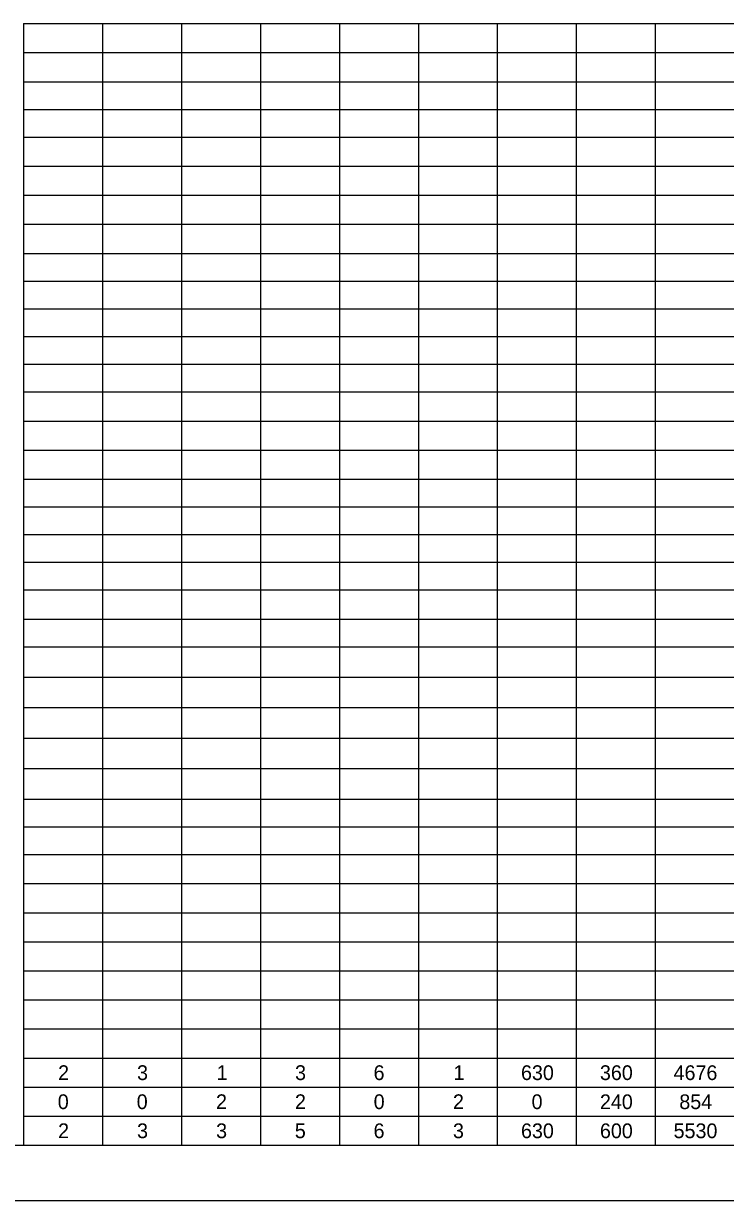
# Model space of a CAD drawing. Extents: x 0 to 34, y 0 to 22.
# Drawn here: x 13.35 to 19.73, y 0 to 10.69 of the extents above; entities that cross this region are included whole.
import ezdxf

# ---------------------------------------------------------------- set-up
doc = ezdxf.new("R2010")
doc.units = 0
for name, color, linetype in [('SH_Border', 7, 'Continuous'), ('SH_Cut_Line', 7, 'Continuous'), ('SH_Text', 7, 'Continuous')]:
    doc.layers.add(name, color=color, linetype=linetype)

msp = doc.modelspace()

# ---------------------------------------------------------------- linework, layer by layer
at = {"layer": 'SH_Border'}
msp.add_lwpolyline([(1.5, 21.5), (33.5, 21.5), (33.5, 0.5), (1.5, 0.5)], close=True, dxfattribs=at)
at = {"layer": 'SH_Cut_Line'}
msp.add_lwpolyline([(0, 0), (34, 0), (34, 22), (0, 22)], close=True, dxfattribs=at)
at = {"layer": 'SH_Text'}
for p, q in [((13.352, 10.692), (14.069, 10.692)), ((13.352, 10.692), (13.352, 10.428)), ((14.069, 10.692), (15.504, 10.692)), ((14.069, 10.692), (14.069, 10.428)), ((14.787, 10.692), (14.787, 10.428)), ((15.504, 10.692), (21.958, 10.692)), ((15.504, 10.692), (15.504, 10.428)), ((16.221, 10.692), (16.221, 10.428)), ((16.938, 10.692), (16.938, 10.428)), ((17.655, 10.692), (17.655, 10.428)), ((18.372, 10.692), (18.372, 10.428)), ((19.09, 10.692), (19.09, 10.428)), ((13.352, 10.428), (14.069, 10.428)), ((13.352, 10.428), (13.352, 10.164)), ((14.069, 10.428), (15.504, 10.428)), ((14.069, 10.428), (14.069, 10.164)), ((14.787, 10.428), (14.787, 10.164)), ((15.504, 10.428), (21.958, 10.428)), ((15.504, 10.428), (15.504, 10.164)), ((16.221, 10.428), (16.221, 10.164)), ((16.938, 10.428), (16.938, 10.164)), ((17.655, 10.428), (17.655, 10.164)), ((18.372, 10.428), (18.372, 10.164)), ((19.09, 10.428), (19.09, 10.164)), ((13.352, 10.164), (14.069, 10.164)), ((13.352, 10.164), (13.352, 9.396)), ((14.069, 10.164), (15.504, 10.164)), ((14.069, 10.164), (14.069, 9.396)), ((14.787, 10.164), (14.787, 9.396)), ((15.504, 10.164), (21.958, 10.164)), ((15.504, 10.164), (15.504, 9.396)), ((16.221, 10.164), (16.221, 9.396)), ((16.938, 10.164), (16.938, 9.396)), ((17.655, 10.164), (17.655, 9.396)), ((18.372, 10.164), (18.372, 9.396)), ((19.09, 10.164), (19.09, 9.396)), ((13.352, 9.912), (14.069, 9.912)), ((14.069, 9.912), (15.504, 9.912)), ((15.504, 9.912), (21.958, 9.912)), ((13.352, 9.66), (14.069, 9.66)), ((14.069, 9.66), (15.504, 9.66)), ((15.504, 9.66), (21.958, 9.66)), ((13.352, 9.396), (14.069, 9.396)), ((13.352, 9.396), (13.352, 9.132)), ((14.069, 9.396), (15.504, 9.396)), ((14.069, 9.396), (14.069, 9.132)), ((14.787, 9.396), (14.787, 9.132)), ((15.504, 9.396), (21.958, 9.396)), ((15.504, 9.396), (15.504, 9.132)), ((16.221, 9.396), (16.221, 9.132)), ((16.938, 9.396), (16.938, 9.132)), ((17.655, 9.396), (17.655, 9.132)), ((18.372, 9.396), (18.372, 9.132)), ((19.09, 9.396), (19.09, 9.132)), ((13.352, 9.132), (14.069, 9.132)), ((13.352, 9.132), (13.352, 8.868)), ((14.069, 9.132), (15.504, 9.132)), ((14.069, 9.132), (14.069, 8.868)), ((14.787, 9.132), (14.787, 8.868)), ((15.504, 9.132), (21.958, 9.132)), ((15.504, 9.132), (15.504, 8.868)), ((16.221, 9.132), (16.221, 8.868)), ((16.938, 9.132), (16.938, 8.868)), ((17.655, 9.132), (17.655, 8.868)), ((18.372, 9.132), (18.372, 8.868)), ((19.09, 9.132), (19.09, 8.868)), ((13.352, 8.868), (14.069, 8.868)), ((13.352, 8.868), (13.352, 8.604)), ((14.069, 8.868), (15.504, 8.868)), ((14.069, 8.868), (14.069, 8.604)), ((14.787, 8.868), (14.787, 8.604)), ((15.504, 8.868), (21.958, 8.868)), ((15.504, 8.868), (15.504, 8.604)), ((16.221, 8.868), (16.221, 8.604)), ((16.938, 8.868), (16.938, 8.604)), ((17.655, 8.868), (17.655, 8.604)), ((18.372, 8.868), (18.372, 8.604)), ((19.09, 8.868), (19.09, 8.604)), ((13.352, 8.604), (14.069, 8.604)), ((13.352, 8.604), (13.352, 7.081)), ((14.069, 8.604), (15.504, 8.604)), ((14.069, 8.604), (14.069, 7.081)), ((14.787, 8.604), (14.787, 7.081)), ((15.504, 8.604), (21.958, 8.604)), ((15.504, 8.604), (15.504, 7.081)), ((16.221, 8.604), (16.221, 7.081)), ((16.938, 8.604), (16.938, 7.081)), ((17.655, 8.604), (17.655, 7.081)), ((18.372, 8.604), (18.372, 7.081)), ((19.09, 8.604), (19.09, 7.081)), ((13.352, 8.352), (14.069, 8.352)), ((14.069, 8.352), (15.504, 8.352)), ((15.504, 8.352), (21.958, 8.352)), ((13.352, 8.1), (14.069, 8.1)), ((14.069, 8.1), (15.504, 8.1)), ((15.504, 8.1), (21.958, 8.1)), ((13.352, 7.849), (14.069, 7.849)), ((14.069, 7.849), (15.504, 7.849)), ((15.504, 7.849), (21.958, 7.849)), ((13.352, 7.597), (14.069, 7.597)), ((14.069, 7.597), (15.504, 7.597)), ((15.504, 7.597), (21.958, 7.597)), ((13.352, 7.345), (14.069, 7.345)), ((14.069, 7.345), (15.504, 7.345)), ((15.504, 7.345), (21.958, 7.345)), ((13.352, 7.081), (14.069, 7.081)), ((13.352, 7.081), (13.352, 6.817)), ((14.069, 7.081), (15.504, 7.081)), ((14.069, 7.081), (14.069, 6.817)), ((14.787, 7.081), (14.787, 6.817)), ((15.504, 7.081), (21.958, 7.081)), ((15.504, 7.081), (15.504, 6.817)), ((16.221, 7.081), (16.221, 6.817)), ((16.938, 7.081), (16.938, 6.817)), ((17.655, 7.081), (17.655, 6.817)), ((18.372, 7.081), (18.372, 6.817)), ((19.09, 7.081), (19.09, 6.817)), ((13.352, 6.817), (14.069, 6.817)), ((13.352, 6.817), (13.352, 5.282)), ((14.069, 6.817), (15.504, 6.817)), ((14.069, 6.817), (14.069, 5.282)), ((14.787, 6.817), (14.787, 5.282)), ((15.504, 6.817), (21.958, 6.817)), ((15.504, 6.817), (15.504, 5.282)), ((16.221, 6.817), (16.221, 5.282)), ((16.938, 6.817), (16.938, 5.282)), ((17.655, 6.817), (17.655, 5.282)), ((18.372, 6.817), (18.372, 5.282)), ((19.09, 6.817), (19.09, 5.282)), ((13.352, 6.553), (14.069, 6.553)), ((14.069, 6.553), (15.504, 6.553)), ((15.504, 6.553), (21.958, 6.553)), ((13.352, 6.301), (14.069, 6.301)), ((14.069, 6.301), (15.504, 6.301)), ((15.504, 6.301), (21.958, 6.301)), ((13.352, 6.049), (14.069, 6.049)), ((14.069, 6.049), (15.504, 6.049)), ((15.504, 6.049), (21.958, 6.049)), ((13.352, 5.798), (14.069, 5.798)), ((14.069, 5.798), (15.504, 5.798)), ((15.504, 5.798), (21.958, 5.798)), ((13.352, 5.546), (14.069, 5.546)), ((14.069, 5.546), (15.504, 5.546)), ((15.504, 5.546), (21.958, 5.546)), ((13.352, 5.282), (14.069, 5.282)), ((13.352, 5.282), (13.352, 4.477)), ((14.069, 5.282), (15.504, 5.282)), ((14.069, 5.282), (14.069, 4.477)), ((14.787, 5.282), (14.787, 4.477)), ((15.504, 5.282), (21.958, 5.282)), ((15.504, 5.282), (15.504, 4.477)), ((16.221, 5.282), (16.221, 4.477)), ((16.938, 5.282), (16.938, 4.477)), ((17.655, 5.282), (17.655, 4.477)), ((18.372, 5.282), (18.372, 4.477)), ((19.09, 5.282), (19.09, 4.477)), ((13.352, 5.03), (14.069, 5.03)), ((14.069, 5.03), (15.504, 5.03)), ((15.504, 5.03), (21.958, 5.03)), ((13.352, 4.753), (14.069, 4.753)), ((14.069, 4.753), (15.504, 4.753)), ((15.504, 4.753), (21.958, 4.753)), ((13.352, 4.477), (14.069, 4.477)), ((13.352, 4.477), (13.352, 3.646)), ((14.069, 4.477), (15.504, 4.477)), ((14.069, 4.477), (14.069, 3.646)), ((14.787, 4.477), (14.787, 3.646)), ((15.504, 4.477), (21.958, 4.477)), ((15.504, 4.477), (15.504, 3.646)), ((16.221, 4.477), (16.221, 3.646)), ((16.938, 4.477), (16.938, 3.646)), ((17.655, 4.477), (17.655, 3.646)), ((18.372, 4.477), (18.372, 3.646)), ((19.09, 4.477), (19.09, 3.646)), ((13.352, 4.2), (14.069, 4.2)), ((14.069, 4.2), (15.504, 4.2)), ((15.504, 4.2), (21.958, 4.2)), ((13.352, 3.923), (14.069, 3.923)), ((14.069, 3.923), (15.504, 3.923)), ((15.504, 3.923), (21.958, 3.923)), ((13.352, 3.646), (14.069, 3.646)), ((13.352, 3.646), (13.352, 2.35)), ((14.069, 3.646), (15.504, 3.646)), ((14.069, 3.646), (14.069, 2.35)), ((14.787, 3.646), (14.787, 2.35)), ((15.504, 3.646), (21.958, 3.646)), ((15.504, 3.646), (15.504, 2.35)), ((16.221, 3.646), (16.221, 2.35)), ((16.938, 3.646), (16.938, 2.35)), ((17.655, 3.646), (17.655, 2.35)), ((18.372, 3.646), (18.372, 2.35)), ((19.09, 3.646), (19.09, 2.35)), ((13.352, 3.395), (14.069, 3.395)), ((14.069, 3.395), (15.504, 3.395)), ((15.504, 3.395), (21.958, 3.395)), ((13.352, 3.143), (14.069, 3.143)), ((14.069, 3.143), (15.504, 3.143)), ((15.504, 3.143), (21.958, 3.143)), ((13.352, 2.879), (14.069, 2.879)), ((14.069, 2.879), (15.504, 2.879)), ((15.504, 2.879), (21.958, 2.879)), ((13.352, 2.614), (14.069, 2.614)), ((14.069, 2.614), (15.504, 2.614)), ((15.504, 2.614), (21.958, 2.614)), ((13.352, 2.35), (14.069, 2.35)), ((13.352, 2.35), (13.352, 1.822)), ((14.069, 2.35), (15.504, 2.35)), ((14.069, 2.35), (14.069, 1.822)), ((14.787, 2.35), (14.787, 1.822)), ((15.504, 2.35), (21.958, 2.35)), ((15.504, 2.35), (15.504, 1.822)), ((16.221, 2.35), (16.221, 1.822)), ((16.938, 2.35), (16.938, 1.822)), ((17.655, 2.35), (17.655, 1.822)), ((18.372, 2.35), (18.372, 1.822)), ((19.09, 2.35), (19.09, 1.822)), ((13.352, 2.086), (14.069, 2.086)), ((14.069, 2.086), (15.504, 2.086)), ((15.504, 2.086), (21.958, 2.086)), ((13.352, 1.822), (14.069, 1.822)), ((13.352, 1.822), (13.352, 1.558)), ((14.069, 1.822), (15.504, 1.822)), ((14.069, 1.822), (14.069, 1.558)), ((14.787, 1.822), (14.787, 1.558)), ((15.504, 1.822), (21.958, 1.822)), ((15.504, 1.822), (15.504, 1.558)), ((16.221, 1.822), (16.221, 1.558)), ((16.938, 1.822), (16.938, 1.558)), ((17.655, 1.822), (17.655, 1.558)), ((18.372, 1.822), (18.372, 1.558)), ((19.09, 1.822), (19.09, 1.558)), ((13.352, 1.558), (14.069, 1.558)), ((13.352, 1.558), (13.352, 1.029)), ((14.069, 1.558), (15.504, 1.558)), ((14.069, 1.558), (14.069, 1.029)), ((14.787, 1.558), (14.787, 1.029)), ((15.504, 1.558), (21.958, 1.558)), ((15.504, 1.558), (15.504, 1.029)), ((16.221, 1.558), (16.221, 1.029)), ((16.938, 1.558), (16.938, 1.029)), ((17.655, 1.558), (17.655, 1.029)), ((18.372, 1.558), (18.372, 1.029)), ((19.09, 1.558), (19.09, 1.029)), ((13.352, 1.293), (14.069, 1.293)), ((14.069, 1.293), (15.504, 1.293)), ((15.504, 1.293), (21.958, 1.293)), ((13.352, 1.029), (14.069, 1.029)), ((13.352, 1.029), (13.352, 0.501)), ((14.069, 1.029), (15.504, 1.029)), ((14.069, 1.029), (14.069, 0.501)), ((14.787, 1.029), (14.787, 0.501)), ((15.504, 1.029), (21.958, 1.029)), ((15.504, 1.029), (15.504, 0.501)), ((16.221, 1.029), (16.221, 0.501)), ((16.938, 1.029), (16.938, 0.501)), ((17.655, 1.029), (17.655, 0.501)), ((18.372, 1.029), (18.372, 0.501)), ((19.09, 1.029), (19.09, 0.501)), ((13.352, 0.765), (14.069, 0.765)), ((14.069, 0.765), (15.504, 0.765)), ((15.504, 0.765), (21.958, 0.765)), ((13.352, 0.501), (14.069, 0.501)), ((14.069, 0.501), (15.504, 0.501)), ((15.504, 0.501), (21.958, 0.501))]:
    msp.add_line(p, q, dxfattribs=at)

# ---------------------------------------------------------------- texts
for s, height, p in [('2', 0.134, (13.666, 1.094)), ('3', 0.134, (14.383, 1.094)), ('1', 0.134, (15.106, 1.094)), ('3', 0.134, (15.818, 1.094)), ('6', 0.134, (16.531, 1.094)), ('1', 0.134, (17.257, 1.094)), ('630', 0.1337, (17.87, 1.094)), ('360', 0.1337, (18.587, 1.094)), ('4676', 0.1337, (19.256, 1.094)), ('0', 0.134, (13.663, 0.83)), ('0', 0.134, (14.38, 0.83)), ('2', 0.134, (15.1, 0.83)), ('2', 0.134, (15.817, 0.83)), ('0', 0.134, (16.532, 0.83)), ('2', 0.134, (17.252, 0.83)), ('0', 0.134, (17.966, 0.83)), ('240', 0.1337, (18.587, 0.83)), ('854', 0.1337, (19.308, 0.83)), ('2', 0.134, (13.666, 0.566)), ('3', 0.134, (14.383, 0.566)), ('3', 0.134, (15.101, 0.566)), ('5', 0.134, (15.816, 0.566)), ('6', 0.134, (16.531, 0.566)), ('3', 0.134, (17.252, 0.566)), ('630', 0.1337, (17.87, 0.566)), ('600', 0.1337, (18.587, 0.566)), ('5530', 0.1337, (19.256, 0.566))]:
    msp.add_text(s, height=height, dxfattribs=at).set_placement(p)

doc.saveas('drawing.dxf')
